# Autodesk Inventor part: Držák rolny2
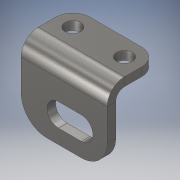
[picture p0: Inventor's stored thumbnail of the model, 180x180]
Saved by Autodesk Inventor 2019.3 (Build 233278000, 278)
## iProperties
Created: 2019-02
Part Number: Držák rolny2
Material: Ocel, měkká, svařovaná
Document SubType Name: Plech
Designer: B-hon
Density: 7.85 g/cm^3
Sheet Metal Rule: Výchozí_mm
Appearance: Pozinkovaná
Author: B-hon
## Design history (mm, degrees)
node "Plocha1"
  sketch "Náčrt1"
    geometry: L1 (-9, 0)-(-30, 0); L2 (-30, 0)-(-30, 26); L3 (-30, 26)-(0, 26); L4 (0, 26)-(0, 9); L5 (-17, 9)-(-9, 9); L6 (-17, 5)-(-9, 5); L7 (-9, 13)-(-17, 13); L8 (-50.597, 35.548)-(1, 35.548); L9 (1, 35.548)-(1, 21.352); L10 (1, 21.352)-(-50.597, 21.352); L11 (-50.597, 21.352)-(-50.597, 35.548); C1 r 14 at (-9, 9); A1 r 4 centre (-17, 9) between (-17, 13) and (-17, 5); A2 r 4 centre (-9, 9) between (-9, 5) and (-9, 13); A3 r 9 centre (-9, 9) between (-9, 0) and (0, 9); 2 further points
    constraints: 24 end point, 6 point on circle, 6 tangent, 5 parallel, 4 centre point, 3 horizontal, 2 perpendicular, 2 point on line, 1 coincident, 1 midpoint
    dimensions: "d0" = 30 distance of L2.end L3.end; "d1" = 26 distance of L1.end L2.end; "d2" = 8 diameter of A2; "d4" = 9 distance from line of L4 L5.end; "d5" = 8 distance of L6.start L6.end; "d6" = 9 radius of A3 (derived); "d7" = 28 diameter of C1; "d8" = 4 distance edge to line of C1 L9; "d9" = 9 distance from line of L1 point (-13, 9)
node "Obruba1"
fillet "Zaoblení1" dims "d31" = 9
fillet "Zaoblení2" dims "d32" = 6
sketch "Náčrt4"
  geometry: A1 r 6 centre (6, 6) between (6, 12) and (0, 6) reference; A2 r 6 centre (24, 6) between (30, 6) and (24, 12) reference; 3 further points
  constraints: 2 coincident
hole "Díra2" sketch "Náčrt4" at (6, 6), (24, 6) diameter "d33" = 5.5; stored, may be unused: countersink angle "d37" = 90 deg, drill point angle "d39" = 0 deg; dims "d34" = 6, "d35" = 4, "d36" = 2, "d38" = 3 (= Tloušťka)
node "Těleso1"
feature "Deska1" dims "d10" = 3 (= Tloušťka)
sketch "Náčrt2"
  geometry: L1 through (-15, 0) direction (1, 0); L2 through (0, 9) direction (0, 1); L3 (0, 18)-(-30, 18); L4 (-30, 18)-(-30, 0)
  constraints: 6 end point, 1 horizontal, 1 perpendicular, 1 vertical
feature "Deska2" dims "d10" = 3 (= Tloušťka), "d11" = 3 (= ŠířkaVýštipu), "d12" = 1.5 (= HloubkaVýštipu), "d13" = 6 (= MinimálníZbytek), "d14" = 3 (= PřechodovýPoloměr), "d15" = 18, "d16" = -90 deg, "d17" = 3 (= PoloměrOhybu), "d18" = 12 (= VelikostRohovéhoVýštipu), "d19" = 3 (= VelikostMezery), "d20" = 3 (= VelikostJacobihoPoloměru), "MezeraVystřižení" = 0.01
feature "Ohyb1" dims "d10" = 3 (= Tloušťka), "d11" = 3 (= ŠířkaVýštipu), "d12" = 1.5 (= HloubkaVýštipu), "d13" = 6 (= MinimálníZbytek), "d14" = 3 (= PřechodovýPoloměr), "d15" = 18, "d16" = -90 deg, "d17" = 3 (= PoloměrOhybu), "MezeraVystřižení" = 0.01
feature "Roh1" dims "d15" = 18, "d16" = -90 deg, "d18" = 12 (= VelikostRohovéhoVýštipu), "d19" = 3 (= VelikostMezery), "d20" = 3 (= VelikostJacobihoPoloměru)
other parameters: "Tloušťka" = 3 (derived), "KSoučinitel" = 4.4, "PoloměrOhybu" = 3 (= Tloušťka), "ŠířkaVýštipu" = 3 (= Tloušťka), "HloubkaVýštipu" = 1.5 (= 0.5 x Tloušťka), "VelikostRohovéhoVýštipu" = 12 (= 4 x Tloušťka), "MinimálníZbytek" = 6 (= 2 x Tloušťka), "PřechodovýPoloměr" = 3 (= PoloměrOhybu), "VelikostJacobihoPoloměru" = 3 (= PoloměrOhybu), "VelikostMezery" = 3 (= Tloušťka)
